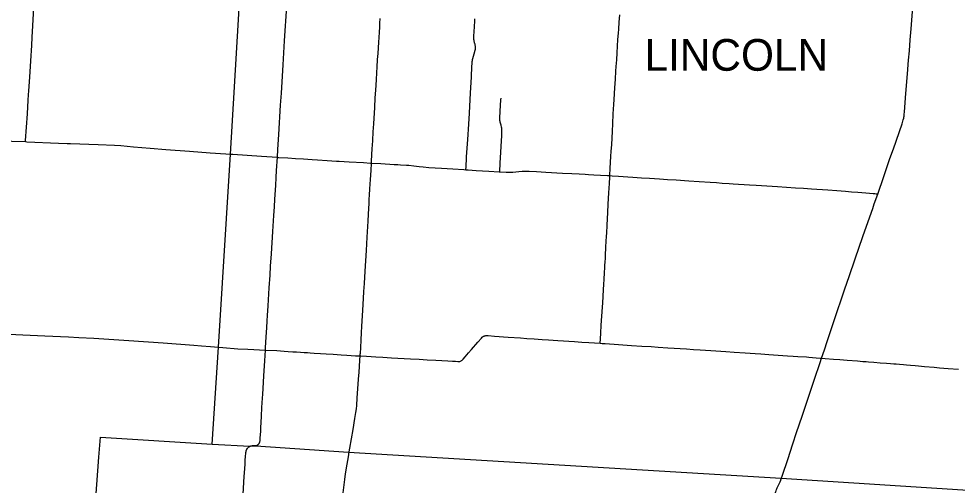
# Model space of a CAD drawing. Extents: x 1815539 to 1947826, y 273303 to 993194.
# Drawn here: x 1848246 to 1874888, y 883973 to 897220 of the extents above; entities that cross this region are included whole.
import ezdxf

# ---------------------------------------------------------------- set-up
doc = ezdxf.new("R2010")
doc.units = 0
for name, color, linetype in [('GM_X_County_Road', 7, 'Continuous'), ('GM_X_Township', 7, 'Continuous'), ('GM_X_Township_Road', 7, 'Continuous'), ('GM_X_Township_Text', 7, 'Continuous')]:
    doc.layers.add(name, color=color, linetype=linetype)

msp = doc.modelspace()

# ---------------------------------------------------------------- linework, layer by layer
at = {"layer": 'GM_X_County_Road'}
for points in [[(1848439, 893732), (1848441, 893763), (1848490, 894516), (1848516, 894909), (1848524, 895057), (1848530, 895171), (1848556, 895564), (1848586, 896023), (1848613, 896465), (1848628, 896694), (1848647, 897022), (1848665, 897366), (1848707, 898070), (1848754, 898873), (1848774, 899250), (1848778, 899288), (1848782, 899332), (1848785, 899370), (1848787, 899396), (1848798, 899459), (1848803, 899489)], [(1855588, 893286), (1855600, 893503), (1855626, 893929), (1855679, 894763), (1855701, 895107), (1855747, 895909), (1855791, 896596), (1855857, 897578), (1855893, 898019), (1855957, 898787), (1855976, 899029)], [(1872630, 892241), (1872801, 892739), (1872978, 893250), (1873076, 893529), (1873325, 894241), (1873357, 894351), (1873368, 894393), (1873372, 894410), (1873374, 894425), (1873378, 894451), (1873380, 894469), (1873383, 894500), (1873389, 894577), (1873430, 895100), (1873476, 895656), (1873507, 896049), (1873529, 896310), (1873555, 896621), (1873580, 896931), (1873609, 897307), (1873629, 897554), (1873637, 897625)], [(1865027, 892765), (1865039, 892981), (1865057, 893308), (1865066, 893456), (1865078, 893636), (1865100, 894028), (1865110, 894241), (1865124, 894520), (1865138, 894782), (1865145, 894929), (1865169, 895256), (1865185, 895501), (1865198, 895730), (1865205, 895861), (1865220, 896058), (1865231, 896254), (1865256, 896630), (1865270, 896810), (1865278, 896924), (1865294, 897120), (1865309, 897333)], [(1858257, 893122), (1858260, 893175), (1858281, 893535), (1858288, 893633), (1858296, 893764), (1858310, 894009), (1858324, 894238), (1858350, 894697), (1858367, 894975), (1858382, 895188), (1858397, 895482), (1858411, 895695), (1858420, 895842), (1858434, 896068), (1858444, 896231), (1858455, 896395), (1858465, 896559), (1858473, 896689), (1858483, 896836), (1858493, 896984), (1858500, 897098), (1858509, 897229)], [(1847079, 893786), (1847571, 893768), (1848046, 893749), (1848439, 893732)], [(1848439, 893732), (1848472, 893730), (1849373, 893692), (1849619, 893681), (1849718, 893678), (1850504, 893646), (1850963, 893628), (1851143, 893618), (1851502, 893583), (1851977, 893545), (1852418, 893510), (1853089, 893460), (1853678, 893416), (1854120, 893386), (1854235, 893378)], [(1854235, 893378), (1854324, 893372)], [(1854324, 893372), (1855134, 893316), (1855588, 893286)], [(1855251, 887811), (1855254, 887874), (1855273, 888185), (1855289, 888446), (1855301, 888643), (1855310, 888792), (1855327, 889068), (1855357, 889576), (1855379, 889936), (1855396, 890197), (1855416, 890541), (1855457, 891179), (1855487, 891638), (1855503, 891883), (1855516, 892096), (1855540, 892489), (1855556, 892717), (1855566, 892914), (1855588, 893286)], [(1855588, 893286), (1855623, 893284), (1855885, 893268), (1856098, 893254), (1856328, 893238), (1856574, 893222), (1856722, 893213), (1857001, 893196), (1857132, 893188), (1857263, 893180), (1857345, 893175), (1857624, 893158), (1858035, 893135), (1858232, 893123), (1858257, 893122)], [(1857940, 887644), (1857942, 887692), (1857944, 887725), (1857953, 887872), (1857966, 888101), (1857977, 888297), (1857987, 888494), (1858011, 888936), (1858021, 889116), (1858032, 889279), (1858044, 889476), (1858057, 889705), (1858078, 890049), (1858095, 890343), (1858113, 890638), (1858135, 891014), (1858161, 891473), (1858173, 891669), (1858190, 891980), (1858197, 892094), (1858204, 892209), (1858214, 892389), (1858229, 892651), (1858246, 892913), (1858257, 893122)], [(1871038, 887583), (1871116, 887821), (1871194, 888054), (1871344, 888505), (1871469, 888879), (1871609, 889299), (1871695, 889547), (1871819, 889903), (1871991, 890399), (1872210, 891035), (1872405, 891592), (1872489, 891834), (1872534, 891964), (1872630, 892241)], [(1846715, 888320), (1846809, 888316), (1846970, 888307), (1847201, 888298), (1847560, 888281), (1848363, 888247), (1848986, 888220), (1849660, 888189), (1849954, 888172), (1850381, 888154), (1850806, 888125), (1851229, 888095), (1851932, 888042), (1852343, 888014), (1853211, 887951), (1853436, 887929), (1853686, 887911), (1853918, 887892)], [(1853918, 887892), (1854041, 887883), (1854469, 887850), (1854750, 887835), (1855251, 887811)], [(1869883, 884123), (1869930, 884257), (1870077, 884709), (1870220, 885146), (1870329, 885473), (1870488, 885938), (1870581, 886218), (1870836, 886981), (1870998, 887462), (1871038, 887583)], [(1869055, 881586), (1869128, 881814), (1869298, 882328), (1869410, 882671), (1869517, 882998), (1869576, 883203), (1869673, 883568), (1869707, 883702), (1869716, 883732), (1869720, 883746), (1869727, 883770), (1869734, 883791), (1869744, 883819), (1869756, 883848), (1869765, 883870), (1869778, 883895), (1869843, 884028), (1869863, 884071), (1869881, 884118), (1869883, 884123)]]:
    msp.add_lwpolyline(points, dxfattribs=at)
at = {"layer": 'GM_X_Township'}
for points in [[(1853740, 885139), (1853912, 887891), (1854256, 893376), (1854601, 899118), (1855968, 899037), (1856227, 902512), (1856354, 904189), (1858556, 904033), (1863007, 903717), (1863265, 907135), (1863306, 907714), (1863375, 908580), (1863406, 908966), (1863544, 910397), (1864246, 910459), (1864806, 910520), (1866935, 910696), (1872022, 911301), (1871903, 909711), (1873264, 909583), (1874571, 909455), (1879532, 909040), (1882082, 908847)], [(1850147, 879854), (1850364, 882693), (1850523, 884772), (1850567, 885340), (1853740, 885139), (1854805, 885081), (1854864, 885092), (1854977, 885091), (1857606, 884909), (1869894, 884174), (1875339, 883824)]]:
    msp.add_lwpolyline(points, dxfattribs=at)
at = {"layer": 'GM_X_Township_Road'}
for points in [[(1860939, 892932), (1860942, 892967), (1860943, 892983), (1860961, 893295), (1860992, 893787), (1861021, 894229), (1861038, 894541), (1861074, 895114), (1861081, 895262), (1861096, 895573), (1861109, 895869), (1861113, 895947), (1861114, 895963), (1861115, 895982), (1861117, 896003), (1861122, 896032), (1861124, 896045), (1861128, 896059), (1861138, 896095), (1861177, 896221), (1861205, 896332), (1861211, 896359), (1861213, 896380), (1861214, 896403), (1861213, 896430), (1861211, 896445), (1861207, 896462), (1861204, 896477), (1861200, 896495), (1861193, 896512), (1861187, 896535), (1861182, 896553), (1861177, 896575), (1861173, 896595), (1861171, 896608), (1861169, 896622), (1861167, 896642), (1861166, 896668), (1861166, 896685), (1861167, 896701), (1861168, 896732), (1861175, 896851), (1861192, 897151), (1861197, 897223)], [(1861897, 892873), (1861898, 892885), (1861911, 893119), (1861956, 893908), (1861962, 894023), (1861961, 894089), (1861959, 894112), (1861954, 894138), (1861937, 894201), (1861914, 894280), (1861909, 894306), (1861906, 894329), (1861904, 894355), (1861904, 894395), (1861916, 894592), (1861935, 894920), (1861940, 894970)], [(1858257, 893122), (1858529, 893106), (1858906, 893083), (1859004, 893078), (1859086, 893075), (1859250, 893065), (1859315, 893060), (1859462, 893042), (1859608, 893024), (1859722, 893012), (1859886, 893000), (1860246, 892977), (1860573, 892955), (1860884, 892935), (1860939, 892932)], [(1860939, 892932), (1860999, 892929), (1861228, 892916), (1861588, 892892), (1861883, 892874), (1861897, 892873)], [(1861897, 892873), (1862079, 892863), (1862161, 892861), (1862210, 892862), (1862276, 892866), (1862439, 892881), (1862537, 892888), (1862636, 892891), (1862734, 892890), (1862947, 892882), (1863209, 892868), (1863684, 892840), (1863946, 892825), (1864159, 892814), (1864323, 892806), (1864421, 892800), (1864568, 892792), (1864764, 892779), (1864961, 892769), (1865027, 892765)], [(1864750, 888006), (1864760, 888128), (1864769, 888291), (1864784, 888520), (1864814, 889028), (1864822, 889158), (1864845, 889518), (1864853, 889682), (1864861, 889813), (1864866, 889894), (1864870, 889943), (1864873, 889992), (1864878, 890057), (1864880, 890105), (1864882, 890138), (1864883, 890170), (1864886, 890218), (1864887, 890234), (1864890, 890299), (1864898, 890430), (1864905, 890577), (1864909, 890658), (1864914, 890740), (1864932, 891050), (1864936, 891132), (1864949, 891361), (1864967, 891722), (1864981, 891951), (1865000, 892278), (1865016, 892540), (1865025, 892720), (1865025, 892737), (1865027, 892765)], [(1865027, 892765), (1865092, 892760), (1865272, 892748), (1865534, 892732), (1865681, 892723), (1865927, 892707), (1866156, 892693), (1866434, 892673), (1866663, 892659), (1866908, 892642), (1867268, 892620), (1867563, 892600), (1867874, 892581), (1868054, 892568), (1868217, 892556), (1868414, 892544), (1868528, 892536), (1868987, 892507), (1869183, 892495), (1869789, 892456), (1870296, 892420), (1870525, 892405), (1870754, 892390), (1871212, 892359), (1871474, 892340), (1871719, 892321), (1871883, 892309), (1872062, 892294), (1872291, 892277), (1872504, 892260), (1872553, 892256), (1872585, 892251), (1872609, 892246), (1872630, 892241)], [(1857940, 887644), (1857956, 887644), (1858119, 887635), (1858381, 887620), (1858578, 887609), (1858823, 887595), (1859363, 887564), (1859609, 887550), (1859838, 887537), (1860084, 887525), (1860427, 887506), (1860558, 887497), (1860640, 887493), (1860706, 887489), (1860738, 887488), (1860755, 887489), (1860771, 887492), (1860786, 887497), (1860801, 887503), (1860816, 887512), (1860829, 887521), (1860841, 887532), (1860865, 887555), (1860919, 887617), (1861013, 887730), (1861099, 887829), (1861281, 888041), (1861378, 888152), (1861401, 888175), (1861413, 888185), (1861441, 888203), (1861456, 888210), (1861471, 888215), (1861487, 888218), (1861504, 888221), (1861536, 888223), (1861569, 888222), (1861749, 888208), (1862141, 888179), (1862485, 888157), (1862665, 888144), (1862877, 888130), (1863106, 888114), (1863286, 888103), (1863548, 888087), (1864023, 888055), (1864235, 888041), (1864432, 888028), (1864750, 888006)], [(1864750, 888006), (1864808, 888003), (1864890, 887998), (1865267, 887973), (1865643, 887946), (1865938, 887927), (1866200, 887909), (1866397, 887896), (1866675, 887877), (1867200, 887844), (1867396, 887829), (1867593, 887815), (1867888, 887795), (1868314, 887769), (1868559, 887751), (1868870, 887731), (1869149, 887712), (1869313, 887702), (1869542, 887687), (1870066, 887651), (1870230, 887641), (1870361, 887632), (1870607, 887616), (1870672, 887611), (1870880, 887595), (1870998, 887586), (1871038, 887583)], [(1855117, 885614), (1855123, 885757), (1855135, 885936), (1855150, 886181), (1855169, 886443), (1855177, 886557), (1855186, 886720), (1855206, 887080), (1855232, 887505), (1855251, 887811)], [(1855251, 887811), (1855568, 887797), (1855780, 887781), (1855895, 887774), (1856026, 887764), (1856128, 887758), (1856244, 887751), (1856344, 887745), (1856442, 887739), (1856521, 887734), (1856635, 887727), (1856811, 887716), (1856974, 887706), (1857170, 887692), (1857399, 887678), (1857563, 887667), (1857808, 887651), (1857940, 887644)], [(1857626, 884922), (1857643, 885024), (1857736, 885557), (1857790, 885864), (1857818, 886042), (1857831, 886140), (1857841, 886238), (1857855, 886451), (1857875, 886712), (1857895, 886990), (1857908, 887186), (1857920, 887349), (1857932, 887529), (1857940, 887644)], [(1871038, 887583), (1871142, 887575), (1871371, 887558), (1871551, 887544), (1871764, 887526), (1872058, 887502), (1872206, 887491), (1872304, 887485), (1872369, 887481), (1872516, 887468), (1872696, 887454), (1872876, 887439), (1872991, 887429), (1873089, 887422), (1873154, 887417), (1873252, 887407), (1873366, 887398), (1873448, 887391), (1873562, 887380), (1873693, 887372), (1873791, 887364), (1873955, 887350), (1874233, 887325), (1874380, 887311), (1874626, 887293), (1874920, 887271)], [(1855098, 885250), (1855098, 885257), (1855100, 885276), (1855102, 885306), (1855113, 885511), (1855117, 885614)], [(1854607, 883551), (1854649, 884223), (1854663, 884442), (1854672, 884577), (1854677, 884663), (1854687, 884807), (1854692, 884868), (1854694, 884887), (1854696, 884907), (1854698, 884928), (1854702, 884949), (1854704, 884959), (1854707, 884971), (1854710, 884979), (1854716, 884991), (1854721, 885001), (1854724, 885006), (1854729, 885012), (1854737, 885021), (1854748, 885034), (1854770, 885053), (1854782, 885063), (1854794, 885071), (1854807, 885078), (1854819, 885083), (1854826, 885086), (1854835, 885090), (1854844, 885092), (1854850, 885094), (1854858, 885095), (1854871, 885097), (1854877, 885098), (1854883, 885098), (1854891, 885099), (1854899, 885099), (1854913, 885099)], [(1854913, 885099), (1854957, 885098), (1854970, 885098), (1854978, 885098), (1854984, 885099), (1854989, 885100), (1854994, 885101), (1854999, 885103), (1855006, 885106), (1855015, 885111), (1855026, 885117), (1855034, 885123), (1855039, 885126), (1855047, 885133), (1855054, 885139), (1855063, 885150), (1855069, 885157), (1855073, 885164), (1855079, 885175), (1855084, 885187), (1855087, 885197), (1855090, 885206), (1855093, 885217), (1855095, 885232), (1855098, 885250)], [(1857362, 882301), (1857363, 882321), (1857373, 882468), (1857386, 882681), (1857401, 882943), (1857416, 883221), (1857424, 883352), (1857438, 883564), (1857448, 883679), (1857475, 883906), (1857504, 884134), (1857525, 884296), (1857566, 884572), (1857602, 884782), (1857626, 884922)]]:
    msp.add_lwpolyline(points, dxfattribs=at)

# ---------------------------------------------------------------- texts
at = {"layer": 'GM_X_Township_Text'}
msp.add_text('LINCOLN', height=900, rotation=0, dxfattribs=at).set_placement((1866007, 895744))

doc.saveas('drawing.dxf')
